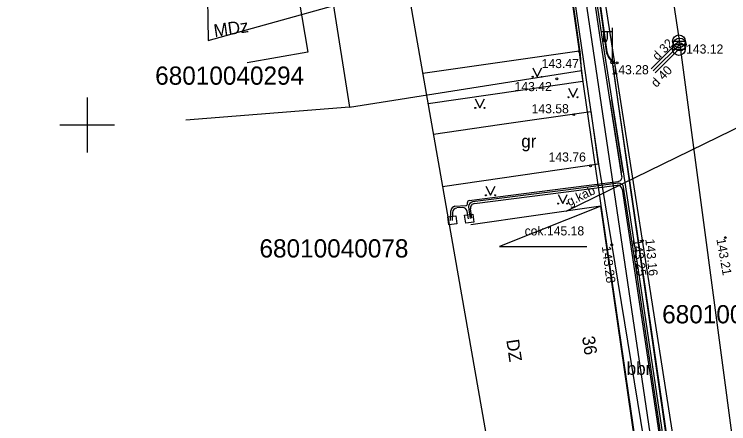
# Model space of a CAD drawing. Extents: x 728710 to 728960, y 272811 to 273475.
# Drawn here: x 728796 to 728835.24, y 272983.61 to 273006.07 of the extents above; entities that cross this region are included whole.
import ezdxf

# ---------------------------------------------------------------- set-up
doc = ezdxf.new("R2010")
doc.units = 0
for name, color, linetype in [('GEOD_ELEM_####_TKST_#', 7, 'Continuous'), ('Level 10', 7, 'Continuous'), ('Level 15', 7, 'Continuous'), ('Level 17', 7, 'Continuous'), ('Level 26', 7, 'Continuous'), ('Level 27', 7, 'Continuous'), ('Level 3', 7, 'Continuous'), ('Level 36', 7, 'Continuous'), ('Level 39', 7, 'Continuous'), ('Level 4', 7, 'Continuous'), ('Level 45', 7, 'Continuous'), ('Level 48', 7, 'Continuous'), ('Level 50', 7, 'Continuous'), ('Level 55', 7, 'Continuous'), ('Level 57', 7, 'Continuous'), ('Level 58', 7, 'Continuous'), ('Level 59', 7, 'Continuous'), ('Level 62', 7, 'Continuous'), ('Level 9', 7, 'Continuous'), ('PNTNO', 7, 'Continuous'), ('RAMI_UZMR_####_####_#', 7, 'Continuous'), ('RELJ_ELEM_####_####_#', 7, 'Continuous'), ('ROBZ_ELEM_####_####_#', 7, 'Continuous'), ('ROBZ_KADS_####_TKST_#', 7, 'Continuous'), ('ROBZ_UZMR_####_####_#', 7, 'Continuous'), ('SAKT_VADV_PKAB_TKST_#', 7, 'Continuous'), ('TERT_ELEM_####_####_#', 7, 'Continuous'), ('TERT_KONT_####_####_#', 7, 'Continuous')]:
    doc.layers.add(name, color=color, linetype=linetype)

msp = doc.modelspace()

# ---------------------------------------------------------------- linework, layer by layer
at = {"layer": 'GEOD_ELEM_####_TKST_#'}
for points in [[(728828.856, 273003.445), (728828.68, 273003.642), (728828.556, 273003.935), (728824.783, 273030.792), (728823.249, 273042.16), (728821.524, 273054.142), (728821.778, 273054.372)], [(728834.432, 272965.54), (728834.353, 272966.059), (728834.337, 272966.173), (728833.056, 272974.371), (728829.783, 272996.939), (728828.856, 273003.445)]]:
    msp.add_lwpolyline(points, dxfattribs=at)
at = {"layer": 'Level 10'}
for p, q in [((728800, 273001.5), (728800, 273000)), ((728798.5, 273000), (728800, 273000)), ((728800, 273000), (728800, 272998.5)), ((728800, 273000), (728801.5, 273000))]:
    msp.add_line(p, q, dxfattribs=at)
at = {"layer": 'Level 15'}
for points in [[(728820.309, 272994.576), (728819.866, 272994.516), (728819.807, 272994.952), (728820.25, 272995.012)], [(728821.241, 272994.675), (728820.799, 272994.614), (728820.739, 272995.049), (728821.181, 272995.11)]]:
    msp.add_lwpolyline(points, close=True, dxfattribs=at)
at = {"layer": 'Level 17'}
for p, q in [((728830.988, 273003.076), (728832.506, 273004.594)), ((728831.096, 273002.968), (728832.548, 273004.42)), ((728831.201, 273002.863), (728832.504, 273004.166))]:
    msp.add_line(p, q, dxfattribs=at)
for points in [[(728830.203, 273020.034), (728832.551, 273004.399)], [(728832.551, 273004.399), (728838.736, 272957.979), (728838.743, 272957.939)]]:
    msp.add_lwpolyline(points, dxfattribs=at)
at = {"layer": 'Level 26'}
for p, q in [((728828.856, 273005.112), (728828.221, 273005.107)), ((728828.356, 273005.108), (728828.356, 273004.716)), ((728828.566, 273005.11), (728828.566, 273004.716)), ((728828.856, 273003.445), (728828.856, 273005.328))]:
    msp.add_line(p, q, dxfattribs=at)
msp.add_circle((728828.856, 273003.445), 0.09, dxfattribs=at)
msp.add_ellipse((728828.461, 273004.716), major_axis=(0, 0.151), ratio=0.695971, start_param=1.570796, end_param=4.712389, dxfattribs=at)
at = {"layer": 'Level 27'}
for points in [[(728827.025, 273003.993), (728827.225, 273002.382)], [(728827.225, 273002.382), (728818.728, 273001.155)]]:
    msp.add_lwpolyline(points, dxfattribs=at)
at = {"layer": 'Level 3'}
for p, q in [((728825.26, 273016.422), (728827.025, 273004.043)), ((728827.025, 273004.043), (728818.436, 273002.818)), ((728828.214, 272995.554), (728821.072, 272994.518)), ((728830.214, 272981.763), (728828.214, 272995.554))]:
    msp.add_line(p, q, dxfattribs=at)
msp.add_lwpolyline([(728811.305, 273008.858), (728812.119, 273004.001), (728808.786, 273003.415)], dxfattribs=at)
at = {"layer": 'Level 36'}
msp.add_line((728829.344, 272997.402), (728828.73, 273001.358), dxfattribs=at)
msp.add_lwpolyline([(728829.442, 272997.418), (728828.828, 273001.373)], dxfattribs=at)
at = {"layer": 'Level 39'}
for p, q in [((728832.155, 273004.594), (728832.857, 273004.594)), ((728832.197, 273004.42), (728832.9, 273004.42)), ((728832.152, 273004.166), (728832.855, 273004.166))]:
    msp.add_line(p, q, dxfattribs=at)
for centre in [(728832.506, 273004.594), (728832.548, 273004.42), (728832.504, 273004.166)]:
    msp.add_circle(centre, 0.351, dxfattribs=at)
at = {"layer": 'Level 4'}
for p, q in [((728825.242, 273017.378), (728827.666, 273000.729)), ((728827.666, 273000.729), (728822.658, 273000)), ((728827.666, 273000.729), (728828.085, 272997.852)), ((728822.658, 273000), (728819.024, 272999.471)), ((728828.085, 272997.852), (728819.526, 272996.606)), ((728828.085, 272997.852), (728831.352, 272977.953))]:
    msp.add_line(p, q, dxfattribs=at)
msp.add_lwpolyline([(728791.727, 273091.506), (728811.654, 273095.023), (728814.654, 273095.178), (728815.22, 273095.032), (728815.785, 273094.657), (728816.384, 273093.154), (728816.384, 273093.154), (728817.477, 273084.163), (728819.263, 273073.354), (728821.261, 273057.957), (728825.757, 273025.679), (728827.763, 273011.141), (728832.943, 272977.993), (728834.913, 272963.328)], dxfattribs=at)
at = {"layer": 'Level 45'}
msp.add_lwpolyline([(728827.662, 273000.753), (728828.074, 272997.85)], dxfattribs=at)
at = {"layer": 'Level 48'}
for centre in [(728827.025, 273004.043), (728829.109, 273003.413), (728825.802, 273002.531), (728826.727, 273000.567), (728827.655, 272997.757), (728830.507, 272993.654), (728835.054, 272993.819), (728828.814, 272993.425)]:
    msp.add_circle(centre, 0.05, dxfattribs=at)
at = {"layer": 'Level 9'}
msp.add_lwpolyline([(728828.214, 272995.554), (728822.659, 272993.337), (728827.454, 272993.337)], dxfattribs=at)
at = {"layer": 'RAMI_UZMR_####_####_#'}
msp.add_line((728826.315, 272995.279), (728843.922, 273003.86), dxfattribs=at)
msp.add_lwpolyline([(728810.894, 273070.336), (728816.634, 273032.011), (728817.26, 273023.998), (728805.412, 273016.121), (728806.079, 273011.62), (728806.601, 273008.097), (728806.659, 273004.632), (728817.58, 273007.699), (728824.279, 272969.525), (728810.963, 272966.628), (728810.935, 272966.213), (728811.098, 272962.191), (728811.981, 272950.771), (728813.612, 272944.45), (728830.483, 272947.485), (728837.542, 272895.947)], dxfattribs=at)
at = {"layer": 'RELJ_ELEM_####_####_#'}
for points in [[(728821.778, 273054.372), (728821.586, 273054.209), (728821.524, 273054.142), (728821.54, 273054.018), (728823.24, 273042.315), (728824.783, 273030.792), (728828.544, 273004.011), (728828.618, 273003.789), (728828.856, 273003.445)], [(728828.856, 273003.445), (728828.857, 273003.328), (728828.884, 273003.229), (728829.195, 273001.031), (728829.783, 272996.939), (728833.068, 272974.423), (728834.337, 272966.173), (728834.366, 272965.827), (728834.432, 272965.54)]]:
    msp.add_lwpolyline(points, dxfattribs=at)
at = {"layer": 'ROBZ_ELEM_####_####_#'}
msp.add_lwpolyline([(728815.186, 273091.969), (728820.435, 273053.684), (728833.431, 272966.054)], dxfattribs=at)
at = {"layer": 'ROBZ_UZMR_####_####_#'}
for p, q in [((728810.138, 273027.96), (728814.417, 273000.979)), ((728827.101, 273003.875), (728825.364, 273016.401)), ((728827.162, 273002.983), (728827.101, 273003.875)), ((728814.417, 273000.979), (728827.162, 273002.983)), ((728830.282, 272981.594), (728827.162, 273002.983)), ((728814.417, 273000.979), (728805.419, 273000.27))]:
    msp.add_line(p, q, dxfattribs=at)
at = {"layer": 'TERT_ELEM_####_####_#'}
for p, q in [((728820.208, 272995.539), (728820.808, 272995.578)), ((728820.901, 272995.686), (728820.896, 272995.746)), ((728819.958, 272994.767), (728819.974, 272995.297))]:
    msp.add_line(p, q, dxfattribs=at)
for points in [[(728815.267, 273094.223), (728815.717, 273091.871), (728816.832, 273085.52), (728817.881, 273078.643), (728818.508, 273074.355), (728819.658, 273066.192), (728820.712, 273058.74), (728821.479, 273053.332), (728822.695, 273044.505), (728823.883, 273036.26), (728825.025, 273027.716), (728825.927, 273020.849), (728826.755, 273015.106), (728828.259, 273004.946), (728828.26, 273004.941)], [(728828.161, 273004.927), (728828.161, 273004.932), (728826.657, 273015.092), (728825.871, 273020.531)], [(728829.378, 272997.186), (728828.161, 273004.926)], [(728828.26, 273004.941), (728829.532, 272996.848), (728830.273, 272992.035), (728831.703, 272982.416), (728832.228, 272978.691), (728832.862, 272974.157)], [(728820.983, 272995.854), (728826.284, 272996.526), (728829.163, 272996.899)], [(728829.191, 272996.802), (728826.297, 272996.427), (728821.176, 272995.778)], [(728821.274, 272995.69), (728826.31, 272996.328), (728829.107, 272996.69)], [(728829.386, 272996.48), (728830.075, 272992.005), (728831.505, 272982.388), (728832.006, 272978.83)], [(728832.751, 272974.233), (728832.129, 272978.677), (728831.604, 272982.402), (728830.174, 272992.02), (728829.47, 272996.592)], [(728820.071, 272995.204), (728820.058, 272994.764)], [(728820.616, 272995.465), (728820.305, 272995.446)], [(728820.941, 272994.854), (728820.879, 272995.254)], [(728820.958, 272995.521), (728820.964, 272995.362), (728821.039, 272994.87)], [(728821.138, 272994.885), (728821.059, 272995.404)]]:
    msp.add_lwpolyline(points, dxfattribs=at)
for centre, radius, start, end in [((728829.131, 272997.147), 0.25, 277.3767, 8.9295), ((728829.223, 272996.554), 0.25, 8.7524, 97.3767), ((728829.139, 272996.442), 0.25, 8.7524, 97.3767), ((728820.802, 272995.678), 0.1, 273.6534, 5.0316), ((728820.995, 272995.755), 0.1, 97.223, 185.0316), ((728821.208, 272995.53), 0.25, 97.223, 182.0772), ((728821.306, 272995.442), 0.25, 97.223, 188.7288), ((728820.224, 272995.29), 0.25, 93.6534, 178.2825), ((728820.321, 272995.196), 0.25, 93.6534, 178.2825), ((728820.632, 272995.216), 0.25, 8.7288, 93.6534)]:
    msp.add_arc(centre, radius, start, end, dxfattribs=at)
at = {"layer": 'TERT_KONT_####_####_#'}
for p, q in [((728824.476, 273003.144), (728824.726, 273002.644)), ((728824.726, 273002.644), (728824.976, 273003.144)), ((728826.441, 273002.023), (728826.691, 273001.523)), ((728826.691, 273001.523), (728826.941, 273002.023)), ((728821.324, 273001.437), (728821.574, 273000.937)), ((728821.574, 273000.937), (728821.824, 273001.437)), ((728821.909, 272996.641), (728822.159, 272996.141)), ((728822.159, 272996.141), (728822.409, 272996.641)), ((728825.873, 272996.186), (728826.123, 272995.686)), ((728826.123, 272995.686), (728826.373, 272996.186))]:
    msp.add_line(p, q, dxfattribs=at)
for centre, radius in [((728824.475, 273002.644), 0.028), ((728824.975, 273002.644), 0.0263), ((728826.441, 273001.522), 0.028), ((728826.941, 273001.522), 0.0263), ((728821.324, 273000.937), 0.028), ((728821.824, 273000.937), 0.0263), ((728821.909, 272996.141), 0.028), ((728822.409, 272996.141), 0.0263), ((728825.872, 272995.685), 0.028), ((728826.372, 272995.685), 0.0263)]:
    msp.add_circle(centre, radius, dxfattribs=at)

# ---------------------------------------------------------------- texts
at = {"layer": 'Level 50'}
msp.add_text('cok.145.18', height=0.5, dxfattribs=at).set_placement((728824.031, 272993.94))
at = {"layer": 'Level 55'}
for s, p in [('d 32', (728831.341, 273003.504)), ('d 40', (728831.267, 273002.03))]:
    msp.add_text(s, height=0.5, rotation=45.5809, dxfattribs=at).set_placement(p)
at = {"layer": 'Level 57'}
for s, p in [(' 143.47', (728824.782, 273003.123)), (' 143.28', (728828.618, 273002.783)), (' 143.42', (728823.293, 273001.857)), (' 143.58', (728824.229, 273000.643)), (' 143.76', (728825.164, 272997.996))]:
    msp.add_text(s, height=0.5, dxfattribs=at).set_placement(p)
for s, rotation, p in [('143.25', 277.4255, (728829.962, 272993.705)), ('143.16', 275.4209, (728830.661, 272993.732)), ('143.21', 280.1558, (728834.562, 272993.731)), ('143.28', 277.4255, (728828.272, 272993.325))]:
    msp.add_text(s, height=0.5, rotation=rotation, dxfattribs=at).set_placement(p)
at = {"layer": 'Level 58'}
for s, p in [('gr', (728823.848, 272998.762)), ('bbr', (728829.637, 272986.29))]:
    msp.add_text(s, height=0.7, dxfattribs=at).set_placement(p)
at = {"layer": 'Level 59'}
for s, rotation, p in [('MDz', 8.4423, (728807.01, 273004.819)), ('DZ', 278.251, (728823.023, 272988.195))]:
    msp.add_text(s, height=0.7, rotation=rotation, dxfattribs=at).set_placement(p)
at = {"layer": 'Level 62'}
msp.add_text('36', height=0.7, rotation=278.251, dxfattribs=at).set_placement((728827.184, 272988.371))
at = {"layer": 'PNTNO'}
msp.add_text('143.12', height=0.5, dxfattribs=at).set_placement((728832.9, 273003.92))
at = {"layer": 'ROBZ_KADS_####_TKST_#'}
for s, p in [('68010040294', (728803.742, 273002.209)), ('68010040078', (728809.47, 272992.73)), ('68010040722', (728831.585, 272989.116))]:
    msp.add_text(s, height=1, dxfattribs=at).set_placement(p)
at = {"layer": 'SAKT_VADV_PKAB_TKST_#'}
msp.add_text('g.kab', height=0.5, rotation=25.9852, dxfattribs=at).set_placement((728826.493, 272995.532))

doc.saveas('drawing.dxf')
